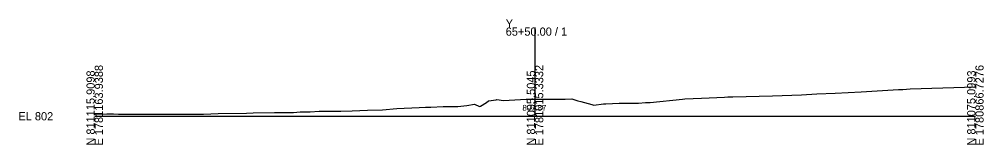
# Model space of a CAD drawing. Extents: x -12583 to 5303, y -44 to 25667.
# Drawn here: x 4974.3 to 5302.8, y 6490.3 to 6533 of the extents above; entities that cross this region are included whole.
import ezdxf

# ---------------------------------------------------------------- set-up
doc = ezdxf.new("R2010")
doc.units = 0
for name, color, linetype in [('Exist Cross Section Cell', 7, 'Continuous'), ('Exist XS Center Line Elevation Label', 7, 'Continuous'), ('Exist XS Ground Line', 7, 'Continuous')]:
    doc.layers.add(name, color=color, linetype=linetype)

msp = doc.modelspace()

# ---------------------------------------------------------------- linework, layer by layer
at = {"layer": 'Exist Cross Section Cell'}
for p, q in [((5150, 6500), (5150, 6530.24)), ((5000, 6500), (5150, 6500)), ((5150, 6500), (5300, 6500))]:
    msp.add_line(p, q, dxfattribs=at)
at = {"layer": 'Exist XS Ground Line'}
for p, q in [((5252.22, 6507.91), (5261.08, 6508.37)), ((5261.08, 6508.37), (5273.84, 6509.07)), ((5273.84, 6509.07), (5275.33, 6509.16)), ((5275.33, 6509.16), (5277.78, 6509.29)), ((5277.78, 6509.29), (5300, 6510.08)), ((5133.41, 6504.74), (5134.12, 6505.31)), ((5134.12, 6505.31), (5136.71, 6505.6)), ((5136.71, 6505.6), (5137.01, 6505.66)), ((5137.01, 6505.66), (5139.2, 6505.42)), ((5139.2, 6505.42), (5147, 6505.77)), ((5147, 6505.77), (5149.72, 6505.87)), ((5149.72, 6505.87), (5157.89, 6505.83)), ((5157.89, 6505.83), (5160.28, 6505.79)), ((5160.28, 6505.79), (5162.53, 6505.91)), ((5162.53, 6505.91), (5164.62, 6505.2)), ((5164.62, 6505.2), (5165.59, 6505.08)), ((5165.59, 6505.08), (5169.29, 6504.02)), ((5189.17, 6504.68), (5200.2, 6505.87)), ((5200.2, 6505.87), (5201.04, 6505.93)), ((5201.04, 6505.93), (5206.66, 6506.18)), ((5206.66, 6506.18), (5214.57, 6506.52)), ((5214.57, 6506.52), (5215.66, 6506.58)), ((5215.66, 6506.58), (5217.38, 6506.63)), ((5217.38, 6506.63), (5230.9, 6507)), ((5230.9, 6507), (5240.74, 6507.33)), ((5240.74, 6507.33), (5245.94, 6507.63)), ((5245.94, 6507.63), (5252.22, 6507.91)), ((5073.37, 6501.55), (5076.42, 6501.68)), ((5076.42, 6501.68), (5083.8, 6501.75)), ((5083.8, 6501.75), (5087.73, 6501.88)), ((5087.73, 6501.88), (5092.92, 6502.06)), ((5092.92, 6502.06), (5098.02, 6502.23)), ((5098.02, 6502.23), (5102.91, 6502.64)), ((5102.91, 6502.64), (5110.57, 6502.96)), ((5110.57, 6502.96), (5112.71, 6503.07)), ((5112.71, 6503.07), (5113.65, 6503.11)), ((5113.65, 6503.11), (5114.46, 6503.13)), ((5114.46, 6503.13), (5118.73, 6503.28)), ((5118.73, 6503.28), (5123.7, 6503.38)), ((5123.7, 6503.38), (5126.73, 6503.65)), ((5126.73, 6503.65), (5129.43, 6504.07)), ((5129.43, 6504.07), (5131.07, 6503.37)), ((5131.07, 6503.37), (5131.45, 6503.41)), ((5131.45, 6503.41), (5133.41, 6504.74)), ((5169.29, 6504.02), (5170.06, 6503.83)), ((5170.06, 6503.83), (5173.28, 6504.19)), ((5173.28, 6504.19), (5174.09, 6504.26)), ((5174.09, 6504.26), (5178.61, 6504.5)), ((5178.61, 6504.5), (5185.27, 6504.51)), ((5185.27, 6504.51), (5187.62, 6504.64)), ((5187.62, 6504.64), (5189.17, 6504.68)), ((5000, 6500.69), (5004.08, 6500.86)), ((5004.08, 6500.86), (5006.36, 6500.83)), ((5006.36, 6500.83), (5008.09, 6500.76)), ((5008.09, 6500.76), (5009.08, 6500.75)), ((5009.08, 6500.75), (5013.9, 6500.7)), ((5013.9, 6500.7), (5017.52, 6500.69)), ((5017.52, 6500.69), (5019.1, 6500.69)), ((5019.1, 6500.69), (5023.09, 6500.68)), ((5023.09, 6500.68), (5023.64, 6500.68)), ((5023.64, 6500.68), (5024.39, 6500.68)), ((5024.39, 6500.68), (5026.6, 6500.68)), ((5026.6, 6500.68), (5027.88, 6500.72)), ((5027.88, 6500.72), (5030.57, 6500.73)), ((5030.57, 6500.73), (5033.85, 6500.73)), ((5033.85, 6500.73), (5037.06, 6500.73)), ((5037.06, 6500.73), (5042.07, 6500.96)), ((5042.07, 6500.96), (5051.72, 6501.11)), ((5051.72, 6501.11), (5053.98, 6501.17)), ((5053.98, 6501.17), (5061.27, 6501.29)), ((5061.27, 6501.29), (5067.7, 6501.29)), ((5067.7, 6501.29), (5070.02, 6501.51)), ((5070.02, 6501.51), (5073.37, 6501.55))]:
    msp.add_line(p, q, dxfattribs=at)

# ---------------------------------------------------------------- texts
at = {"layer": 'Exist Cross Section Cell'}
for s, p in [('Y', (5140, 6530.24)), ('65+50.00 / 1', (5140, 6527.44)), ('EL 802', (4974, 6498.6))]:
    msp.add_text(s, height=2.8, dxfattribs=at).set_placement(p)
for s, p in [('N 811115.9098', (5000, 6490)), ('E 1781163.9388', (5002.8, 6490)), ('N 811095.5045', (5150, 6490)), ('E 1781015.3332', (5152.8, 6490)), ('N 811075.0993', (5300, 6490)), ('E 1780866.7276', (5302.8, 6490))]:
    msp.add_text(s, height=2.8, rotation=90, dxfattribs=at).set_placement(p)
at = {"layer": 'Exist XS Center Line Elevation Label'}
msp.add_text('807.87', height=2, dxfattribs=at).set_placement((5145.7, 6501.87))

doc.saveas('drawing.dxf')
